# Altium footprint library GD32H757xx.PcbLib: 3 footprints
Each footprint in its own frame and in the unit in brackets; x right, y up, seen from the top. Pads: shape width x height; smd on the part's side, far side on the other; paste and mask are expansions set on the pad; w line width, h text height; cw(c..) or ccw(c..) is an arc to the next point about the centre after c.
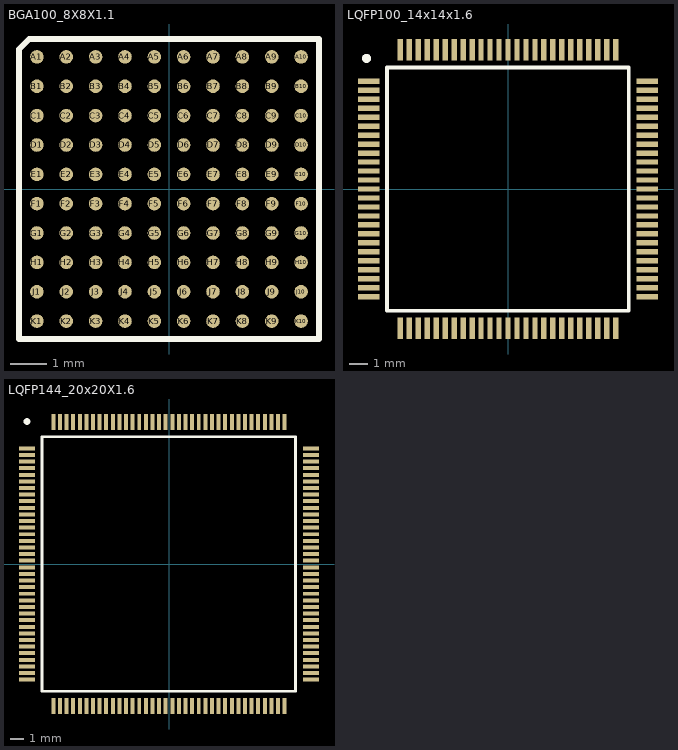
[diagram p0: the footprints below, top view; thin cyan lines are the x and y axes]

## BGA100_8X8X1.1 [mm]
pads (100):
  round 0.37 smd: A1(-3.6,3.6) A2(-2.8,3.6) A3(-2,3.6) A4(-1.2,3.6) A5(-0.4,3.6) A6(0.4,3.6) A7(1.2,3.6) A8(2,3.6) A9(2.8,3.6) A10(3.6,3.6) B1(-3.6,2.8) B2(-2.8,2.8) B3(-2,2.8) B4(-1.2,2.8) B5(-0.4,2.8) B6(0.4,2.8) B7(1.2,2.8) B8(2,2.8) B9(2.8,2.8) B10(3.6,2.8) C1(-3.6,2) C2(-2.8,2) C3(-2,2) C4(-1.2,2) C5(-0.4,2) C6(0.4,2) C7(1.2,2) C8(2,2) C9(2.8,2) C10(3.6,2) D1(-3.6,1.2) D2(-2.8,1.2) D3(-2,1.2) D4(-1.2,1.2) D5(-0.4,1.2) D6(0.4,1.2) D7(1.2,1.2) D8(2,1.2) D9(2.8,1.2) D10(3.6,1.2) E1(-3.6,0.4) E2(-2.8,0.4) E3(-2,0.4) E4(-1.2,0.4) E5(-0.4,0.4) E6(0.4,0.4) E7(1.2,0.4) E8(2,0.4) E9(2.8,0.4) E10(3.6,0.4) F1(-3.6,-0.4) F2(-2.8,-0.4) F3(-2,-0.4) F4(-1.2,-0.4) F5(-0.4,-0.4) F6(0.4,-0.4) F7(1.2,-0.4) F8(2,-0.4) F9(2.8,-0.4) F10(3.6,-0.4) G1(-3.6,-1.2) G2(-2.8,-1.2) G3(-2,-1.2) G4(-1.2,-1.2) G5(-0.4,-1.2) G6(0.4,-1.2) G7(1.2,-1.2) G8(2,-1.2) G9(2.8,-1.2) G10(3.6,-1.2) H1(-3.6,-2) H2(-2.8,-2) H3(-2,-2) H4(-1.2,-2) H5(-0.4,-2) H6(0.4,-2) H7(1.2,-2) H8(2,-2) H9(2.8,-2) H10(3.6,-2) J1(-3.6,-2.8) J2(-2.8,-2.8) J3(-2,-2.8) J4(-1.2,-2.8) J5(-0.4,-2.8) J6(0.4,-2.8) J7(1.2,-2.8) J8(2,-2.8) J9(2.8,-2.8) J10(3.6,-2.8) K1(-3.6,-3.6) K2(-2.8,-3.6) K3(-2,-3.6) K4(-1.2,-3.6) K5(-0.4,-3.6) K6(0.4,-3.6) K7(1.2,-3.6) K8(2,-3.6) K9(2.8,-3.6) K10(3.6,-3.6)
Top Overlay:
  lines w0.152: -4.089,-4.089 -4.089,3.81 -3.81,4.089 4.089,4.089 4.089,-4.089 -4.089,-4.089
3D body "BGA100C80P10X10_800X800X110.step": height 1.1, standoff 0, extent -4,-4 4,4

## LQFP100_14x14x1.6 [mm]
pads (100):
  rect 1.2x0.3 smd: 1(-7.75,6) 2(-7.75,5.5) 3(-7.75,5) 4(-7.75,4.5) 5(-7.75,4) 6(-7.75,3.5) 7(-7.75,3) 8(-7.75,2.5) 9(-7.75,2) 10(-7.75,1.5) 11(-7.75,1) 12(-7.75,0.5) 13(-7.75,0) 14(-7.75,-0.5) 15(-7.75,-1) 16(-7.75,-1.5) 17(-7.75,-2) 18(-7.75,-2.5) 19(-7.75,-3) 20(-7.75,-3.5) 21(-7.75,-4) 22(-7.75,-4.5) 23(-7.75,-5) 24(-7.75,-5.5) 25(-7.75,-6) 51(7.75,-6) 52(7.75,-5.5) 53(7.75,-5) 54(7.75,-4.5) 55(7.75,-4) 56(7.75,-3.5) 57(7.75,-3) 58(7.75,-2.5) 59(7.75,-2) 60(7.75,-1.5) 61(7.75,-1) 62(7.75,-0.5) 63(7.75,0) 64(7.75,0.5) 65(7.75,1) 66(7.75,1.5) 67(7.75,2) 68(7.75,2.5) 69(7.75,3) 70(7.75,3.5) 71(7.75,4) 72(7.75,4.5) 73(7.75,5) 74(7.75,5.5) 75(7.75,6)
  rect 0.3x1.2 smd: 26(-6,-7.75) 27(-5.5,-7.75) 28(-5,-7.75) 29(-4.5,-7.75) 30(-4,-7.75) 31(-3.5,-7.75) 32(-3,-7.75) 33(-2.5,-7.75) 34(-2,-7.75) 35(-1.5,-7.75) 36(-1,-7.75) 37(-0.5,-7.75) 38(0,-7.75) 39(0.5,-7.75) 40(1,-7.75) 41(1.5,-7.75) 42(2,-7.75) 43(2.5,-7.75) 44(3,-7.75) 45(3.5,-7.75) 46(4,-7.75) 47(4.5,-7.75) 48(5,-7.75) 49(5.5,-7.75) 50(6,-7.75) 76(6,7.75) 77(5.5,7.75) 78(5,7.75) 79(4.5,7.75) 80(4,7.75) 81(3.5,7.75) 82(3,7.75) 83(2.5,7.75) 84(2,7.75) 85(1.5,7.75) 86(1,7.75) 87(0.5,7.75) 88(0,7.75) 89(-0.5,7.75) 90(-1,7.75) 91(-1.5,7.75) 92(-2,7.75) 93(-2.5,7.75) 94(-3,7.75) 95(-3.5,7.75) 96(-4,7.75) 97(-4.5,7.75) 98(-5,7.75) 99(-5.5,7.75) 100(-6,7.75)
Top Overlay:
  circle w0.254: c-7.877,7.27 r0.127
  lines w0.203: -6.734,-6.782 6.728,-6.782 6.728,6.762 -6.734,6.762 -6.734,-6.782
3D body "TSQFP50P1600X1600X160-100N.step": height 1.6, standoff 0, extent -8,-8 8,8

## LQFP144_20x20X1.6 [mm]
pads (144):
  rect 1.2x0.3 smd: 1(-10.75,8.75) 2(-10.75,8.25) 3(-10.75,7.75) 4(-10.75,7.25) 5(-10.75,6.75) 6(-10.75,6.25) 7(-10.75,5.75) 8(-10.75,5.25) 9(-10.75,4.75) 10(-10.75,4.25) 11(-10.75,3.75) 12(-10.75,3.25) 13(-10.75,2.75) 14(-10.75,2.25) 15(-10.75,1.75) 16(-10.75,1.25) 17(-10.75,0.75) 18(-10.75,0.25) 19(-10.75,-0.25) 20(-10.75,-0.75) 21(-10.75,-1.25) 22(-10.75,-1.75) 23(-10.75,-2.25) 24(-10.75,-2.75) 25(-10.75,-3.25) 26(-10.75,-3.75) 27(-10.75,-4.25) 28(-10.75,-4.75) 29(-10.75,-5.25) 30(-10.75,-5.75) 31(-10.75,-6.25) 32(-10.75,-6.75) 33(-10.75,-7.25) 34(-10.75,-7.75) 35(-10.75,-8.25) 36(-10.75,-8.75) 73(10.75,-8.75) 74(10.75,-8.25) 75(10.75,-7.75) 76(10.75,-7.25) 77(10.75,-6.75) 78(10.75,-6.25) 79(10.75,-5.75) 80(10.75,-5.25) 81(10.75,-4.75) 82(10.75,-4.25) 83(10.75,-3.75) 84(10.75,-3.25) 85(10.75,-2.75) 86(10.75,-2.25) 87(10.75,-1.75) 88(10.75,-1.25) 89(10.75,-0.75) 90(10.75,-0.25) 91(10.75,0.25) 92(10.75,0.75) 93(10.75,1.25) 94(10.75,1.75) 95(10.75,2.25) 96(10.75,2.75) 97(10.75,3.25) 98(10.75,3.75) 99(10.75,4.25) 100(10.75,4.75) 101(10.75,5.25) 102(10.75,5.75) 103(10.75,6.25) 104(10.75,6.75) 105(10.75,7.25) 106(10.75,7.75) 107(10.75,8.25) 108(10.75,8.75)
  rect 0.3x1.2 smd: 37(-8.75,-10.75) 38(-8.25,-10.75) 39(-7.75,-10.75) 40(-7.25,-10.75) 41(-6.75,-10.75) 42(-6.25,-10.75) 43(-5.75,-10.75) 44(-5.25,-10.75) 45(-4.75,-10.75) 46(-4.25,-10.75) 47(-3.75,-10.75) 48(-3.25,-10.75) 49(-2.75,-10.75) 50(-2.25,-10.75) 51(-1.75,-10.75) 52(-1.25,-10.75) 53(-0.75,-10.75) 54(-0.25,-10.75) 55(0.25,-10.75) 56(0.75,-10.75) 57(1.25,-10.75) 58(1.75,-10.75) 59(2.25,-10.75) 60(2.75,-10.75) 61(3.25,-10.75) 62(3.75,-10.75) 63(4.25,-10.75) 64(4.75,-10.75) 65(5.25,-10.75) 66(5.75,-10.75) 67(6.25,-10.75) 68(6.75,-10.75) 69(7.25,-10.75) 70(7.75,-10.75) 71(8.25,-10.75) 72(8.75,-10.75) 109(8.75,10.75) 110(8.25,10.75) 111(7.75,10.75) 112(7.25,10.75) 113(6.75,10.75) 114(6.25,10.75) 115(5.75,10.75) 116(5.25,10.75) 117(4.75,10.75) 118(4.25,10.75) 119(3.75,10.75) 120(3.25,10.75) 121(2.75,10.75) 122(2.25,10.75) 123(1.75,10.75) 124(1.25,10.75) 125(0.75,10.75) 126(0.25,10.75) 127(-0.25,10.75) 128(-0.75,10.75) 129(-1.25,10.75) 130(-1.75,10.75) 131(-2.25,10.75) 132(-2.75,10.75) 133(-3.25,10.75) 134(-3.75,10.75) 135(-4.25,10.75) 136(-4.75,10.75) 137(-5.25,10.75) 138(-5.75,10.75) 139(-6.25,10.75) 140(-6.75,10.75) 141(-7.25,10.75) 142(-7.75,10.75) 143(-8.25,10.75) 144(-8.75,10.75)
Top Overlay:
  circle w0.254: c-10.75,10.782 r0.127
  lines w0.203: -9.607,-9.627 9.57,-9.627 9.57,9.639 -9.607,9.639 -9.607,-9.627
3D body "TSQFP50P2200X2200X160-144N.step": height 1.6, standoff 0, extent -11,-11 11,11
